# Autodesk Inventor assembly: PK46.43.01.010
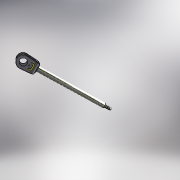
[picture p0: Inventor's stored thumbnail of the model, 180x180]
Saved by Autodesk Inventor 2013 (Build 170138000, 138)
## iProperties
Shininess: 64.0
Length Units: 11269
Angle Units: 11279
Time Units: 11290
Mass Units: 11283
Length Display Precision: 3
Angle Display Precision: 2
Compacted: True
Created: 2004-11
Part Number: PK46.43.01.010
Document SubType Name: Assembly
Designer: ELarisa
Manufacturer: Standard
Standards Organization: Custom
Density: 0.0
Volumn: 0.0
Area: 0.0
PropertySet Name: Model Information
Control State: 0
Master: False
Checked Out: False
Checked Out Date: 2008-10-09
Last Check In Date: 2008-10-09
Author: ELarisa
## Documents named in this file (4)
- C:\Product Design Suite 2013 Test Drive\Dynamic Simulation\Workspace\Assy, Chassis, Front\PK46.43.01.010.iam
- C:\Product Design Suite 2013 Test Drive\Dynamic Simulation\Workspace\Assy, Chassis, Front\PK46.43.01.001.ipt
- C:\Product Design Suite 2013 Test Drive\Dynamic Simulation\Workspace\Assy, Chassis, Front\PK46.43.01.008.ipt
- C:\Product Design Suite 2013 Test Drive\Dynamic Simulation\Workspace\Assy, Chassis, Front\PK30.25.00.005.ipt
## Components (3 placed, 3 different names)
1. PK46.43.01.001:1 — Insert:1
2. PK46.43.01.008:1 — Угол:1, Mate:2, Insert:1, Mate:3
3. PK30.25.00.005:1 — Mate:2, Mate:3
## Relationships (4: Mate 2, Angle 1, Insert 1)
- Угол:1 [Angle]: PK46.43.01.008:1
- Mate:2: PK46.43.01.008:1 ↔ PK30.25.00.005:1
- Insert:1: PK46.43.01.001:1 ↔ PK46.43.01.008:1
- Mate:3: PK46.43.01.008:1 ↔ PK30.25.00.005:1
